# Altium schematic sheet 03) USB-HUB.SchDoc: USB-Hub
size A3; DocumentNumber: 3; SheetNumber: 3; SheetTotal: 10
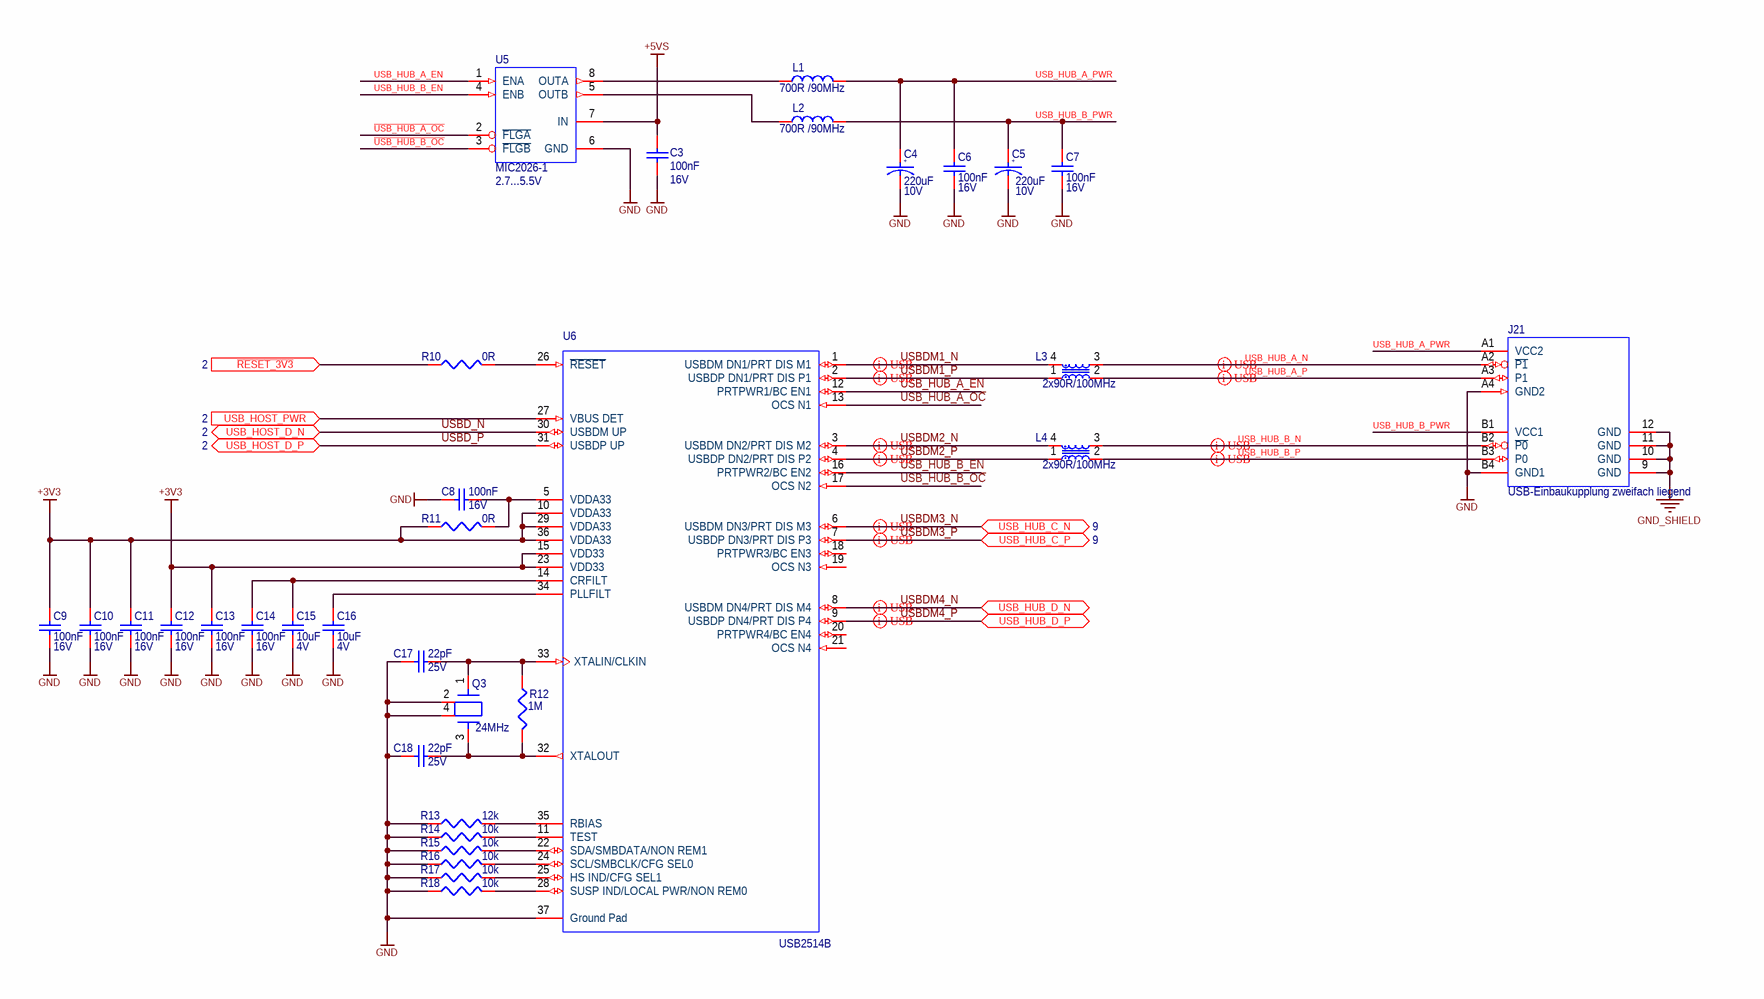
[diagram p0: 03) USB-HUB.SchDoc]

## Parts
C3  100nF  Voltage: 16V  [C0402]
C4  220uF  Voltage: 10V  [C_2312]
C5  220uF  Voltage: 10V  [C_2312]
C6  100nF  Voltage: 16V  [C0402]
C7  100nF  Voltage: 16V  [C0402]
C8  100nF  Voltage: 16V  [C0402]
C9  100nF  Voltage: 16V  [C0402]
C10  100nF  Voltage: 16V  [C0402]
C11  100nF  Voltage: 16V  [C0402]
C12  100nF  Voltage: 16V  [C0402]
C13  100nF  Voltage: 16V  [C0402]
C14  100nF  Voltage: 16V  [C0402]
C15  10uF  Voltage: 4V  [C0402]
C16  10uF  Voltage: 4V  [C0402]
C17  22pF  Voltage: 25V  [C0402]
C18  22pF  Voltage: 25V  [C0402]
J21  USB-Einbaukupplung zweifach liegend  [LUMBERG-2410-03]
L1  700R /90MHz  [L1206]
L2  700R /90MHz  [L1206]
L3  2x90R/100MHz  [USBSHOCK4-0805-12]
L4  2x90R/100MHz  [USBSHOCK4-0805-12]
Q3  24MHz  [XTALD-4-302X205M]
R10  0R  [R0402]
R11  0R  [R0402]
R12  1M  [R0402]
R13  12k  [R0402]
R14  10k  [R0402]
R15  10k  [R0402]
R16  10k  [R0402]
R17  10k  [R0402]
R18  10k  [R0402]
U5  MIC2026-1  Voltage: 2.7...5.5V  [MIC2026]
U6  USB2514B  [USB2514]

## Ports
USB_HOST_D_N (bidir, see 2), USB_HOST_D_P (bidir, see 2), USB_HOST_PWR (in, see 2), USB_HUB_C_N (bidir, see 9), USB_HUB_C_P (bidir, see 9), USB_HUB_D_N (bidir), USB_HUB_D_P (bidir), ~{RESET_3V3} (in, see 2)

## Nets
+3V3: C9.2 C10.2 C11.2 C12.2 C13.2 R11.1 U6.10(VDDA33) U6.15(VDD33) U6.23(VDD33) U6.29(VDDA33) U6.36(VDDA33)
+5VS: C3.2 U5.7(IN)
GND: C3.1 C4.2 C5.2 C6.1 C7.1 C8.2 C9.1 C10.1 C11.1 C12.1 C13.1 C14.1 C15.1 C16.1 C17.1 C18.1 J21.A4(GND2) J21.B4(GND1) Q3.2(Y4) Q3.4(Y3) R13.1 R14.1 R15.1 R16.1 R17.1 R18.1 U5.6(GND) U6.37(Ground_Pad)
GND_SHIELD: J21.9(GND) J21.10(GND) J21.11(GND) J21.12(GND)
~{RESET_3V3}: R10.1 ; port ~{RESET_3V3}
~{USB_HUB_A_OC}: U5.2(~{FLGA}) U6.13(OCS_N1)
~{USB_HUB_B_OC}: U5.3(~{FLGB}) U6.17(OCS_N2)
USB_HOST_PWR: U6.27(VBUS_DET) ; port USB_HOST_PWR
USB_HUB_A_EN: U5.1(ENA) U6.12(PRTPWR1/BC_EN1)
USB_HUB_A_N: J21.A2(~{P1}) L3.3
USB_HUB_A_P: J21.A3(P1) L3.2
USB_HUB_A_PWR: C4.1 C6.2 J21.A1(VCC2) L1.1
USB_HUB_B_EN: U5.4(ENB) U6.16(PRTPWR2/BC_EN2)
USB_HUB_B_N: J21.B2(~{P0}) L4.3
USB_HUB_B_P: J21.B3(P0) L4.2
USB_HUB_B_PWR: C5.1 C7.2 J21.B1(VCC1) L2.1
USBD_N: U6.30(USBDM_UP) ; port USB_HOST_D_N
USBD_P: U6.31(USBDP_UP) ; port USB_HOST_D_P
USBDM1_N: L3.4 U6.1(USBDM_DN1/PRT_DIS_M1)
USBDM1_P: L3.1 U6.2(USBDP_DN1/PRT_DIS_P1)
USBDM2_N: L4.4 U6.3(USBDM_DN2/PRT_DIS_M2)
USBDM2_P: L4.1 U6.4(USBDP_DN2/PRT_DIS_P2)
USBDM3_N: U6.6(USBDM_DN3/PRT_DIS_M3) ; port USB_HUB_C_N
USBDM3_P: U6.7(USBDP_DN3/PRT_DIS_P3) ; port USB_HUB_C_P
USBDM4_N: U6.8(USBDM_DN4/PRT_DIS_M4) ; port USB_HUB_D_N
USBDM4_P: U6.9(USBDP_DN4/PRT_DIS_P4) ; port USB_HUB_D_P
NetC8_1: C8.1 R11.2 U6.5(VDDA33)
NetC14_2: C14.2 C15.2 U6.14(CRFILT)
NetC16_2: C16.2 U6.34(PLLFILT)
NetC17_2: C17.2 Q3.1(Y2) R12.1 U6.33(XTALIN/CLKIN)
NetC18_2: C18.2 Q3.3(Y1) R12.2 U6.32(XTALOUT)
NetL1_2: L1.2 U5.8(OUTA)
NetL2_2: L2.2 U5.5(OUTB)
NetR10_2: R10.2 U6.26(~{RESET})
NetR13_2: R13.2 U6.35(RBIAS)
NetR14_2: R14.2 U6.11(TEST)
NetR15_2: R15.2 U6.22(SDA/SMBDATA/NON_REM1)
NetR16_2: R16.2 U6.24(SCL/SMBCLK/CFG_SEL0)
NetR17_2: R17.2 U6.25(HS_IND/CFG_SEL1)
NetR18_2: R18.2 U6.28(SUSP_IND/LOCAL_PWR/NON_REM0)

Not connected (* = marked no-connect by the designer): U6 18(PRTPWR3/BC_EN3) 19(OCS_N3) 20(PRTPWR4/BC_EN4) 21(OCS_N4)

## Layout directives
differential pair; differential pair class USB: USB_HUB_A_N, USB_HUB_A_P, USB_HUB_B_N, USB_HUB_B_P, USBDM1_N, USBDM1_P, USBDM2_N, USBDM2_P, USBDM3_N, USBDM3_P, USBDM4_N, USBDM4_P

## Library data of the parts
C3 C6-C14 = 380: 100nF  10%  16V  X7R  0402; FS-EDV-Nummer: B.CKV.42; Class: Capacitor Ceramic; Tolerance: 10; ID: 380
C4 C5 = 718: 220uF  20%  10V  2312  Typ: C; FS-EDV-Nummer: B.CTA.16; Class: Capacitor Tantal; Tolerance: 20; ID: 718
C15 C16 = 394: 10uF  20%  4V  X5R  0402; FS-EDV-Nummer: B.CKV.77; Class: Capacitor Ceramic; Tolerance: 20; ID: 394
C17 C18 = 384: 22pF  5%  25V  C0G/NP0  0402; FS-EDV-Nummer: B.CKV.47; Class: Capacitor Ceramic; Tolerance: 5; ID: 384
J21 = 2704: USB-Einbaukupplung zweifach liegend Typ A; Part Number: 2410 03; FS-EDV-Nummer: B.MBU.1R4PL.2; Class: Connector; ID: 2704
L1 L2 = 2705: WE-CBF  25%  700R  90MHz  EMI  1206; Part Number: 74279218; FS-EDV-Nummer: B.EMVFER.5; Class: Ferit; ID: 2705
L3 L4 = 2698: Common Mode Choke  20%  2x 90 Ohm  0805; FS-EDV-Nummer: B.EMVFER.11; Power: 400mA; ID: 2698
Q3 = 2757: 24MHz 12pF 3.2x2.5 SMD; Part Number: Q22FA2380038014; ID: 2757; Class: Crystal; FS-EDV-Nummer: B.Q.28
R10 R11 = 173: 0R 1/16W max 5% SMD 0402; FS-EDV-Nummer: B.R0R0.1; Tolerance: 5; ID: 173
R12 = 180: 1M 1/16W 1% SMD 0402; FS-EDV-Nummer: B.R1M0.1; Tolerance: 1; ID: 180
R13 = 183: 12k 1/16W 1% SMD 0402; FS-EDV-Nummer: B.R12K.2; Tolerance: 1; ID: 183
R14-R18 = 170: 10k 1/16W 1% SMD 0402; FS-EDV-Nummer: B.R10K.3; Tolerance: 1; ID: 170
U5 = 1285: MIC2026-1 USB Power Switch; FS-EDV-Nummer: B.ICIF.110; Class: IC; ID: 1285
U6 = 1255: USB2514B C-Temp.; ID: 1255; Class: IC; FS-EDV-Nummer: B.ICIF.80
